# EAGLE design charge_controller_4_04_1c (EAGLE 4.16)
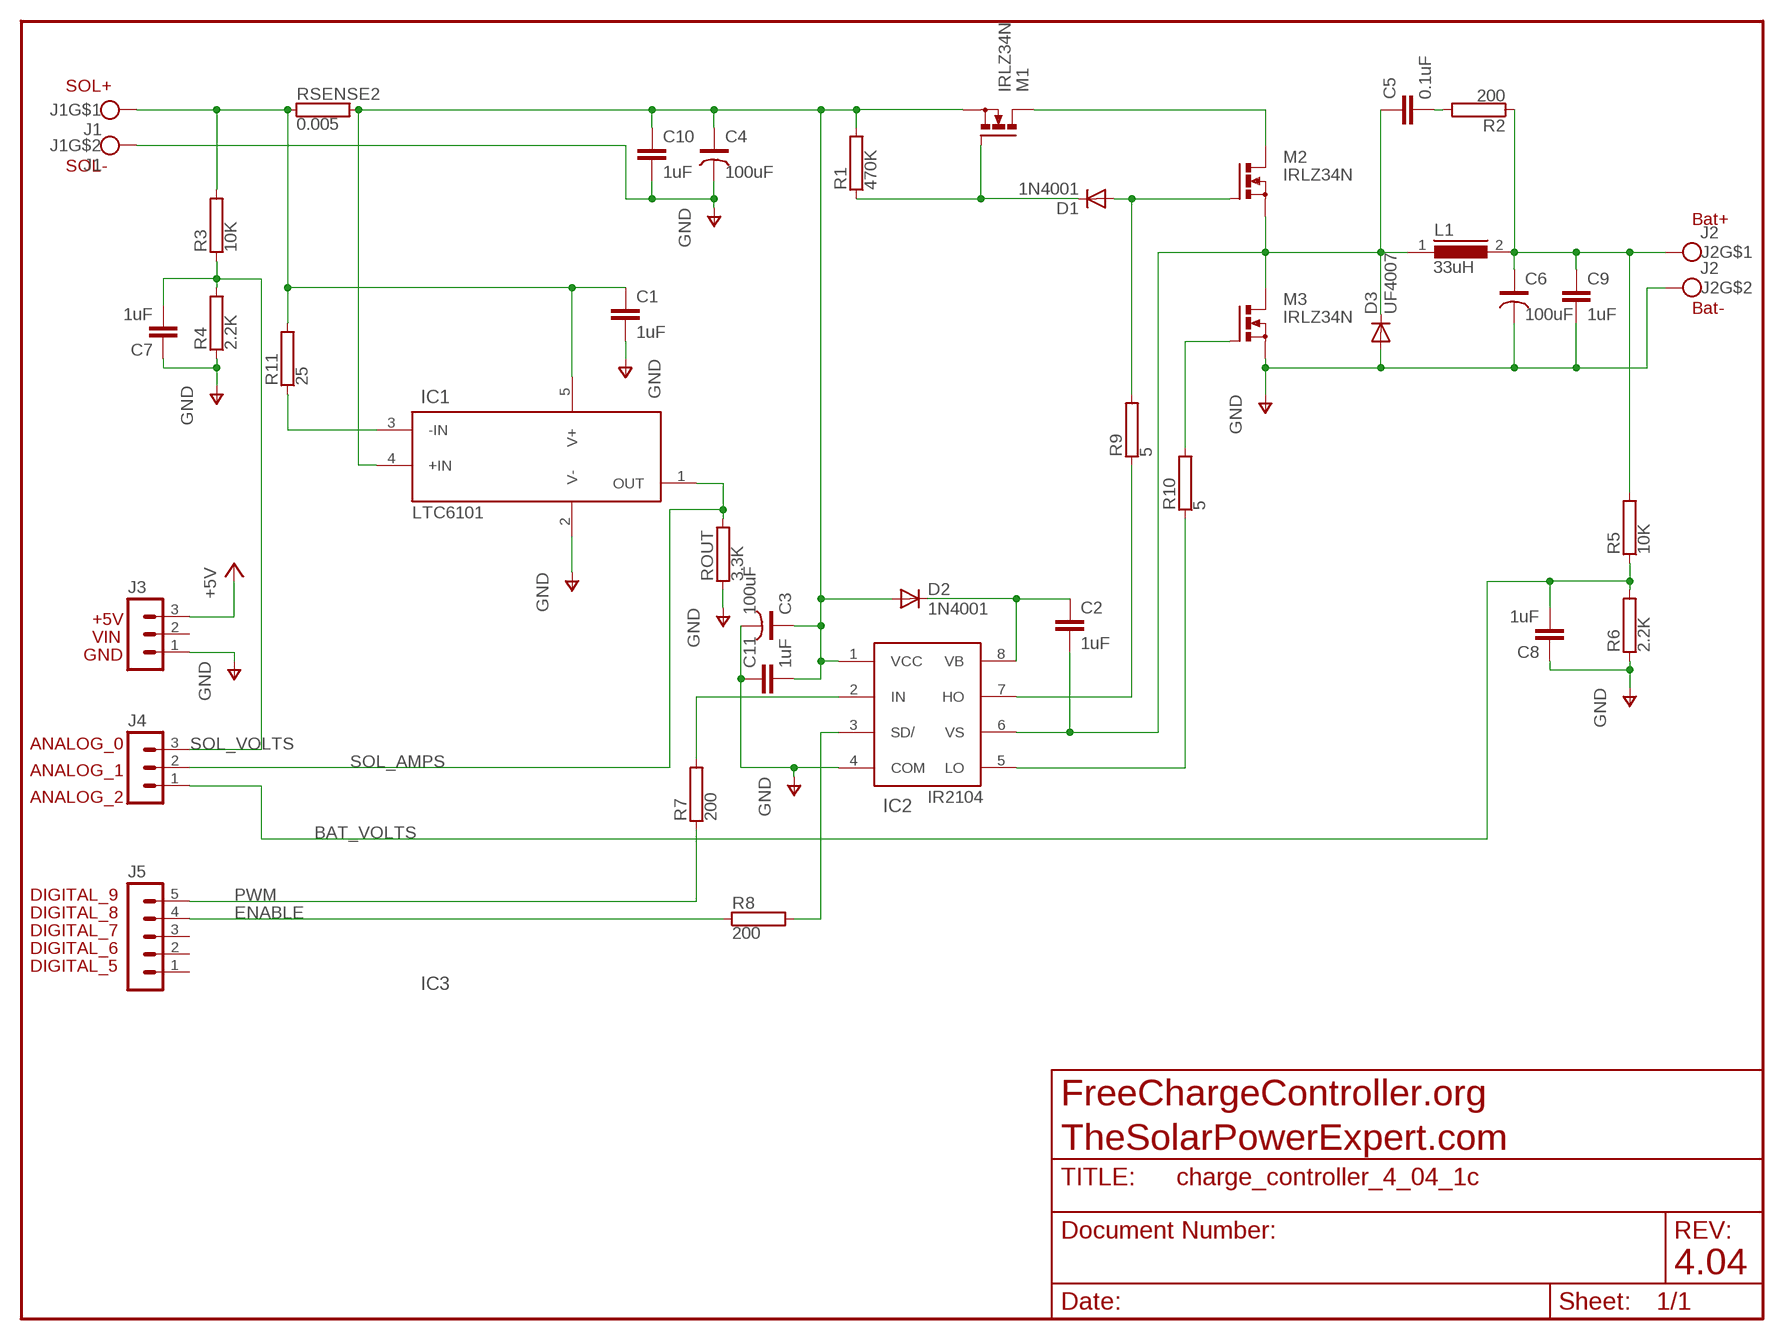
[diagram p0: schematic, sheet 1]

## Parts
C1  1uF  C2.5/2  [C2.5-2]
C2  1uF  C2.5/2  [C2.5-2]
C3  100uF  CAP_POLARIZED  [CAP_POLARIZED]
C4  100uF  CAP_POLARIZED  [CAP_POLARIZED]
C5  0.1uF  C2.5/2  [C2.5-2]
C6  100uF  CAP_POLARIZED  [CAP_POLARIZED]
C7  1uF  C2.5/2  [C2.5-2]
C8  1uF  C2.5/2  [C2.5-2]
C9  1uF  C2.5/2  [C2.5-2]
C10  1uF  C2.5/2  [C2.5-2]
C11  1uF  C2.5/2  [C2.5-2]
D1  1N4001  DIODE  [DO35-10]
D2  1N4001  DIODE  [DO35-10]
D3  UF4007  DIODE  [DO35-10]
IC1  LTC6101B  [TSOT23-5]
IC2  IR2104  [DIP08]
J1  J1  SCREW_TERMINALS  [SCREW_TERMINALS]
J2  J2  SCREW_TERMINALS  [SCREW_TERMINALS]
J3  MA03-1  [MA03-1]
J4  MA03-1  [MA03-1]
J5  MA05-1  [MA05-1]
L1  33uH  A26GFC  [A26GFC]
M1  IRLZ34N  IRFP240  [TO247BV]
M2  IRLZ34N  IRFP240  [TO247BV]
M3  IRLZ34N  IRFP240  [TO247BV]
R1  470K  R  [DO35-10]
R2  200  R  [DO35-10]
R3  10K  R  [DO35-10]
R4  2.2K  R  [DO35-10]
R5  10K  R  [DO35-10]
R6  2.2K  R  [DO35-10]
R7  200  R  [DO35-10]
R8  200  R  [DO35-10]
R9  5  R  [DO35-10]
R10  5  R  [DO35-10]
R11  25  R  [DO35-10]
ROUT  3.3K  R  [DO35-10]
RSENSE2  0.005  RKWP333  [KWP333]

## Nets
+5V: J3.3
BAT_VOLTS: C8.2 J4.1 R5.A R6.C
ENABLE: J5.4 R8.A
N$1: C1.1 IC1.5(V+) J1.1 R3.C R11.C RSENSE2.1
N$2: IC2.3(SD/) R8.C
N$3: IC1.3(-IN) R11.A
N$4: M3.G R10.C
N$5: D1.C M1.G R1.A
N$6: M1.D M2.D
N$7: IC2.7(HO) R9.A
N$8: IC2.2(IN) R7.C
N$9: C3.1 C4.1 C10.1 C11.2 D2.A IC1.4(+IN) IC2.1(VCC) M1.S R1.C RSENSE2.2
N$10: C2.1 D2.C IC2.8(VB)
N$11: C2.2 C5.1 D3.C IC2.6(VS) L1.1 M2.S M3.D
N$12: C6.1 C9.1 J2.1 L1.2 R2.A R5.C
N$13: IC2.5(LO) R10.A
N$14: D1.A M2.G R9.C
N$15: C5.2 R2.C
PWM: J5.5 R7.A
SOL_AMPS: IC1.1(OUT) J4.2 ROUT.C
SOL_VOLTS: C7.2 J4.3 R3.A R4.C
V-: C1.2 C3.2 C4.2 C6.2 C7.1 C8.1 C9.2 C10.2 C11.1 D3.A IC1.2(V-) IC2.4(COM) J1.2 J2.2 J3.1 M3.S R4.A R6.A ROUT.A ; supply symbol labelled GND
Unconnected: J3.2 J5.1 J5.2 J5.3

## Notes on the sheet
- SOL+
- SOL-
- Bat+
- Bat-
- IC1
- LTC6101
- +5V
- VIN
- GND
- ANALOG_0
- ANALOG_1
- ANALOG_2 | IR2104
- IC2
- DIGITAL_9
- DIGITAL_8
- DIGITAL_7
- DIGITAL_6
- DIGITAL_5
- IC3
- FreeChargeController.org
- TheSolarPowerExpert.com
- 4.04

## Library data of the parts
C1 C2 C5 C7-C11 = capacitor-wima:C: CAPACITOR
C3 C4 C6 = MyLibrary:CAP_POLARIZED
D1-D3 = MyLibrary:DIODE
IC1 = MyLibrary:LTC6101B
IC2 = MyLibrary:IR2104: IR2104 MOSFET H-Bridge Driver
J1 J2 = MyLibrary:SCREW_TERMINALS
J3 J4 = con-lstb:MA03-1: PIN HEADER
J5 = con-lstb:MA05-1: PIN HEADER
L1 = inductors:A26GFC: INDUCTOR
M1-M3 = transistor-power:IRFP240: HEXFET Power MosFet Source: http://www.irf.com/
R1-R11 ROUT = resistor-power2:R: Power Resitor
RSENSE2 = resistor-power:R: Power Resitor

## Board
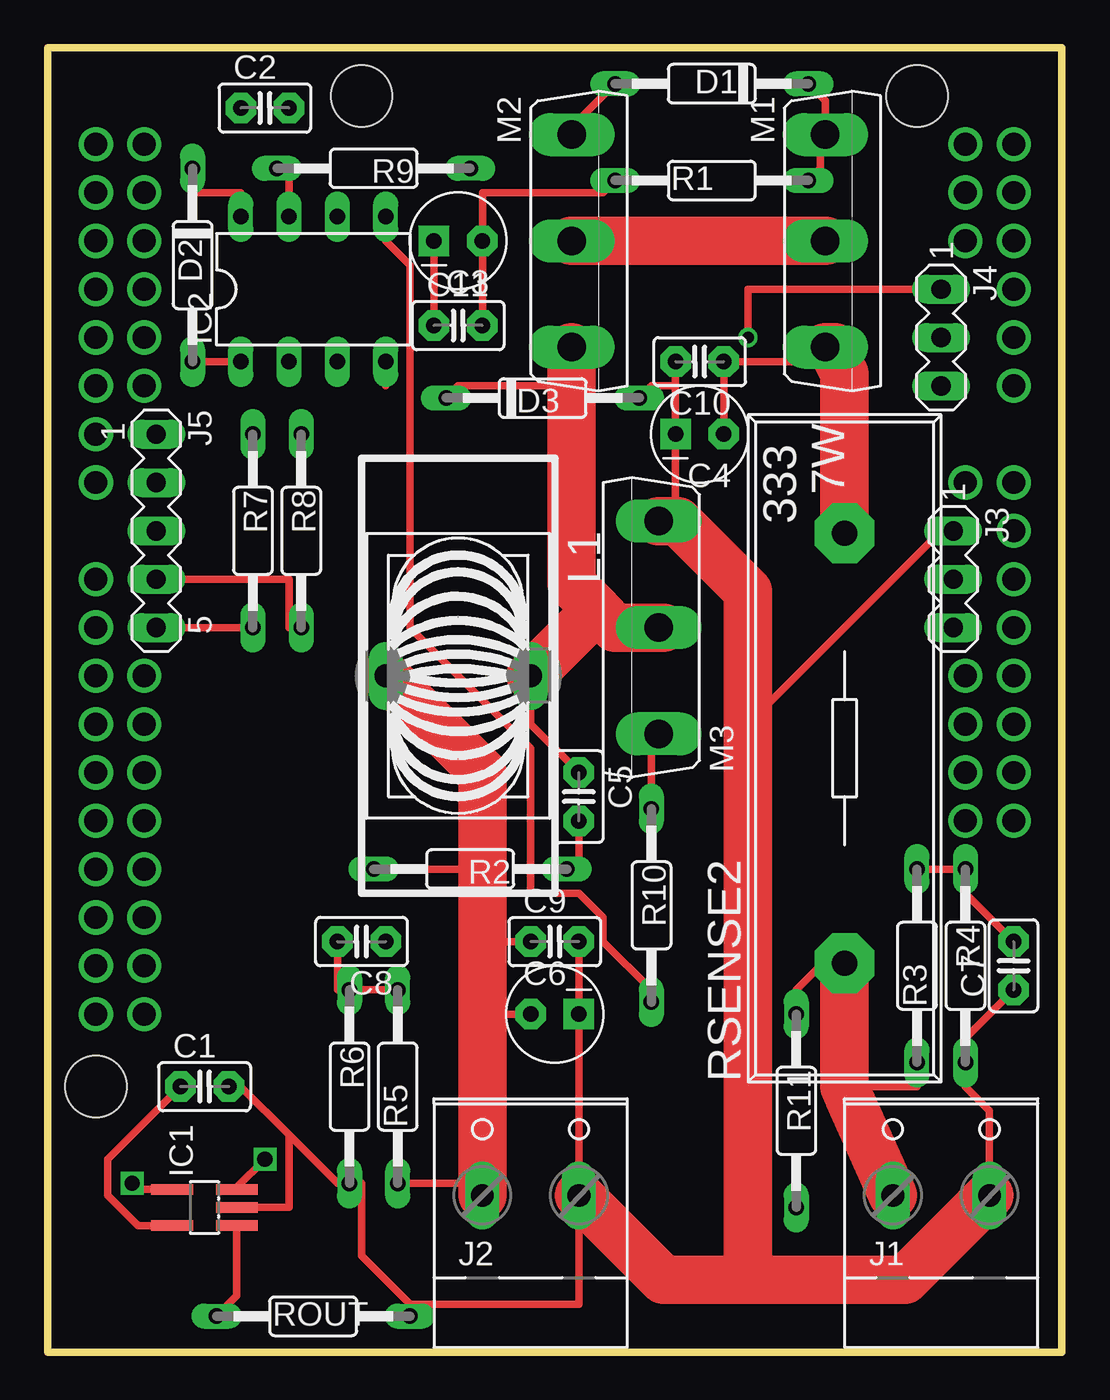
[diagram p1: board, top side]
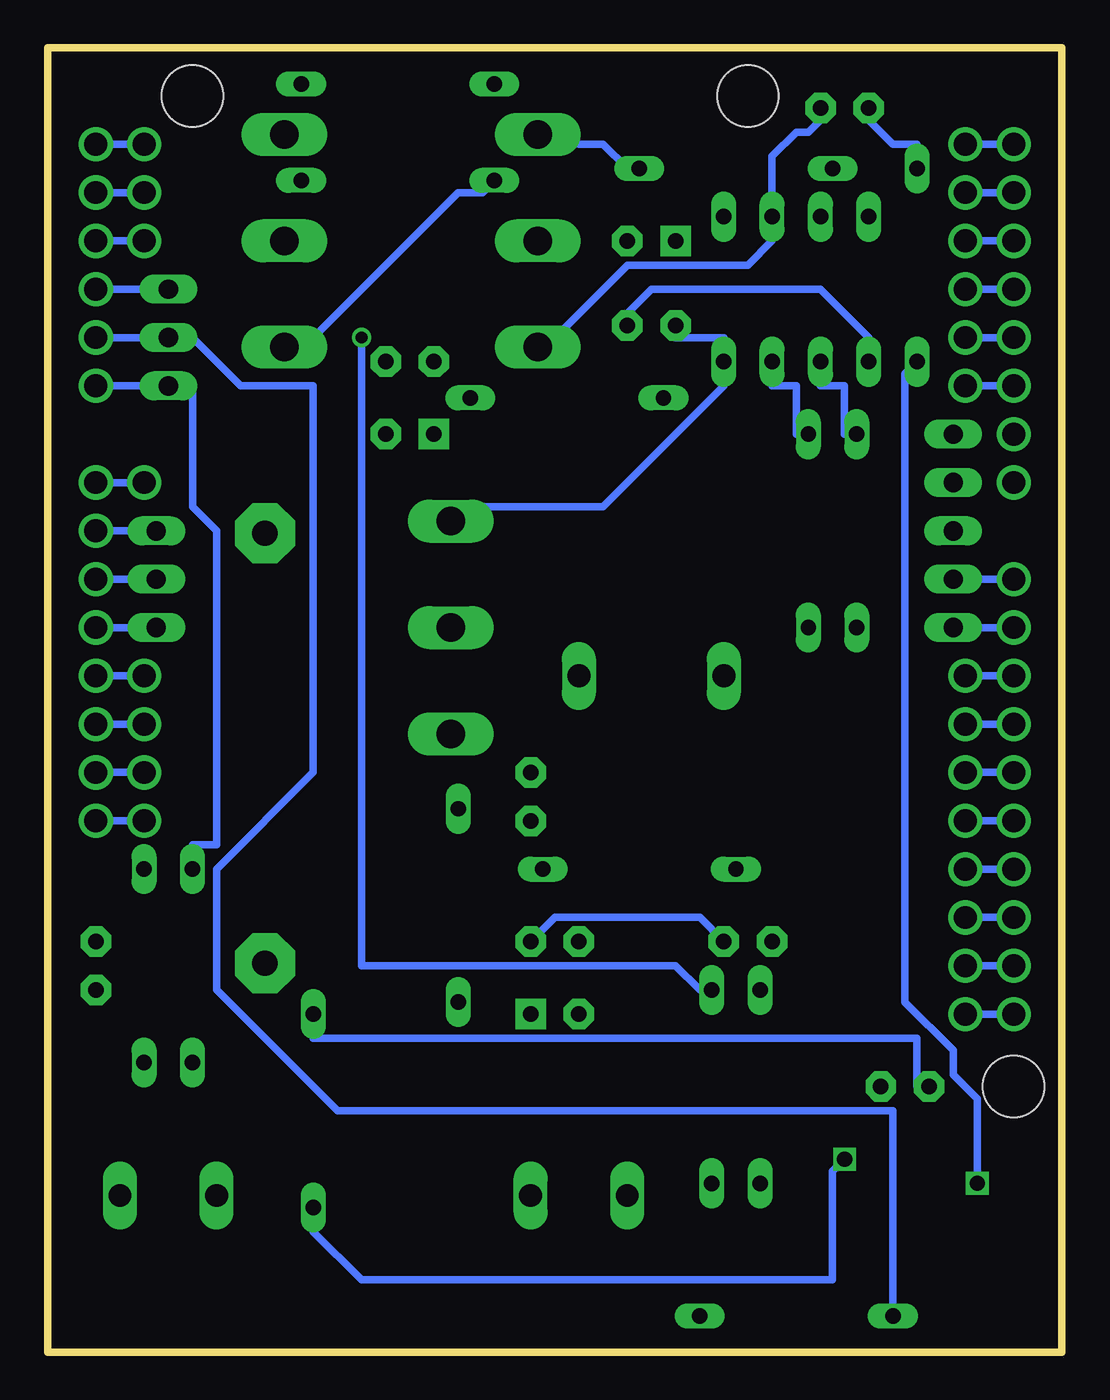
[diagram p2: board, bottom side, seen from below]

Size 53.34 x 68.58 mm. Coordinates in mm from the lower left corner, seen from the top.
Outline: 53.34,0 53.34,68.58 0,68.58 0,0 53.34,0
Copper layers (1*16): Top 0.035mm / dielectric 1.5mm / Bottom 0.035mm
Design rules "default": minimum track width 16mil, minimum drill 24mil, track to track 8mil, track to pad 8mil, pad to pad 8mil, via to via 8mil, smd to smd 8mil, copper to edge 40mil, drill to drill 8mil, minimum pad ring 10mil, minimum via ring 8mil, stop-mask expansion 4mil, vias tented up to drill 0mil, thermal gap 10mil
Holes 3.23 mm at 45.72,66.04 16.51,66.04 2.54,13.97

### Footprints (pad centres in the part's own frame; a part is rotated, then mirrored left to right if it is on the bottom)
C2.5-2 = drill 0.813 pad 1.6 octagon: 1 -1.27,0; 2 1.27,0
CAP_POLARIZED = drill 0.813 pad 1.6 octagon: 1 -1.27,0 | drill 0.813 pad 1.6 square: 2 1.27,0
DO35-10 = drill 0.813 long: A 5.08,0; C -5.08,0
TSOT23-5 = smd 0.55 x 2.2: 1 -0.95,-1.7; 2 0,-1.7; 3 0.95,-1.7; 4 0.95,1.7; 5 -0.95,1.7
DIP08 = drill 0.813 long: 1 -3.81,-3.81; 2 -1.27,-3.81; 3 1.27,-3.81; 4 3.81,-3.81; 5 3.81,3.81; 6 1.27,3.81; 7 -1.27,3.81; 8 -3.81,3.81
SCREW_TERMINALS = drill 1.194 long: 1 -2.54,-0.635; 2 2.54,-0.635
MA03-1 = drill 1.016 long: 1 -2.54,0; 2 0,0; 3 2.54,0
MA05-1 = drill 1.016 long: 1 -5.08,0; 2 -2.54,0; 3 0,0; 4 2.54,0; 5 5.08,0
A26GFC = drill 1.194 long: 1 0,3.81; 2 0,-3.81
TO247BV = drill 1.499 long: D 0,-2.921; G -5.588,-2.921; S 5.588,-2.921
KWP333 = drill 1.321 pad 3.15 octagon: 1 -11.303,0; 2 11.303,0

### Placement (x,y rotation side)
C1  8.26,13.97 0 top
C2  11.43,65.41 0 top
C3  21.59,58.42 180 top
C4  34.29,48.26 180 top
C5  27.94,29.21 270 top
C6  26.67,17.78 0 top
C7  50.8,20.32 90 top
C8  16.51,21.59 180 top
C9  26.67,21.59 0 top
C10  34.29,52.07 180 top
C11  21.59,53.98 0 top
D1  34.92,66.67 180 top
D2  7.62,57.15 270 top
D3  26.04,50.16 0 top
IC1  8.26,7.62 90 top
IC2  13.97,55.88 0 top
J1  46.99,8.89 0 top
J2  25.4,8.89 0 top
J3  47.62,40.64 270 top
J4  46.99,53.34 270 top
J5  5.71,43.18 270 top
L1  21.59,35.56 270 top
M1  43.81,58.42 270 top
M2  30.48,58.42 270 top
M3  29.21,38.1 90 top
R1  34.92,61.59 0 top
R2  22.23,25.4 180 top
R3  45.72,20.32 90 top
R4  48.26,20.32 270 top
R5  18.41,13.97 90 top
R6  15.88,13.97 270 top
R7  10.79,43.18 270 top
R8  13.34,43.18 270 top
R9  17.14,62.23 180 top
R10  31.75,23.5 270 top
R11  39.37,12.7 270 top
ROUT  13.97,1.91 0 top
RSENSE2  41.91,31.75 90 top

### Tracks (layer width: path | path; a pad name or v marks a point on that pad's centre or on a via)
BAT_VOLTS  (via drill 0.61, 1.2)
  Top 0.406: R5.A R6.C 15.24,19.05 C8.2 | v36.83,53.34 36.83,55.88 J4.1
  Bottom 0.406: J4.1 v50.8,55.88 | v36.83,53.34 36.83,20.32 20.32,20.32 19.05,19.05 R5.A
ENABLE
  Top 0.406: R8.A 12.7,38.1 12.7,40.64 J5.4
N$1
  Top 0.406: R11.C 39.37,19.05 40.64,20.32 RSENSE2.1 | R3.C 45.72,13.97 43.18,13.97 42.12,13.5 | IC1.5 4.76,6.67 3.17,8.26 3.17,10.16 C1.1
  Top 2.54: J1.1 42.12,13.5 41.91,13.97 RSENSE2.1
  Bottom 0.406: C1.1 7.62,13.97 7.62,16.51 39.37,16.51 R11.C
N$2
  Bottom 0.406: R8.C 13.97,48.26 13.97,50.8 15.24,50.8 IC2.3
N$3  (via drill 0.8)
  Top 0.406: IC1.3 9.96,8.69 v11.43,10.16
  Bottom 0.406: R11.A 39.37,6.35 36.83,3.81 12.06,3.81 12.06,9.53 v11.43,10.16
N$4
  Top 0.406: R10.C 31.75,31.75 M3.G
N$5
  Top 0.406: R1.A 40.64,62.23 40.64,63.5 M1.G 40.89,65.79 D1.C
N$6
  Top 2.54: M2.D M1.D
N$7
  Top 0.406: R9.A 12.7,62.23 IC2.7
N$8
  Bottom 0.406: R7.C 11.43,48.26 11.43,50.8 12.7,50.8 IC2.2
N$9  (via drill 0.8)
  Top 0.406: C4.1 C10.1 39.37,52.07 M1.S | R1.C 29.21,60.96 22.86,60.96 C3.1 C11.2 | D2.A IC2.1 | IC1.4 4.76,8.57 v4.45,8.89
  Top 2.54: M1.S 41.4,52.83 41.27,52.7 41.91,51.44 RSENSE2.2
  Bottom 0.406: IC2.1 10.16,53.34 12.7,55.88 21.59,55.88 22.86,54.61 C11.2 | M1.S 39.37,53.34 31.75,60.96 30.48,60.96 R1.C | D2.A 8.26,51.44 8.26,18.41 5.71,15.88 5.71,14.61 4.45,13.34 v4.45,8.89
N$10
  Top 0.406: D2.C 7.62,60.96 10.16,60.96 IC2.8
  Bottom 0.406: C2.1 10.16,64.77 8.89,63.5 7.62,63.5 D2.C
N$11
  Top 0.406: C5.1 25.4,33.02 L1.1 | D3.C 21.59,50.8 27.56,50.8
  Top 2.54: M2.S 27.56,50.8 27.56,40.39 28.89,39.05 | 28.89,39.05 29.84,38.1 M3.D 32.38,38.1 | L1.1 28.89,39.05
  Bottom 0.406: C2.2 12.7,64.77 13.34,64.14 13.97,64.14 15.24,62.87 IC2.6 15.24,58.42 16.51,57.15 22.86,57.15 26.67,53.34 M2.S
N$12
  Top 0.406: R5.C 22.86,8.89 | 22.86,25.4 R2.A | 22.86,17.78 C6.1 | 22.86,21.59 C9.1
  Top 2.54: J2.1 22.86,8.89 22.86,17.78 22.86,21.59 22.86,25.4 22.86,30.48 L1.2
N$13
  Top 0.406: R10.A 31.75,19.05 29.21,21.59 29.21,22.86 27.94,24.13 25.4,24.13 25.4,31.75 19.05,38.1 19.05,57.15 17.78,58.42 IC2.5
N$14
  Top 0.406: M2.G 27.56,64.39 D1.A
  Bottom 0.406: R9.C 22.86,62.23 24.13,63.5 25.4,63.5 M2.G
N$15
  Top 0.406: C5.2 27.94,25.4 R2.C
N$17  (via drill 1.2)
  Bottom 0.406: v2.54,38.1 6.35,38.1
N$30  (via drill 1.2)
  Bottom 0.406: v2.54,63.5 v5.08,63.5
N$31  (via drill 1.2)
  Bottom 0.406: v2.54,60.96 v5.08,60.96
N$32  (via drill 1.2)
  Bottom 0.406: v2.54,58.42 v5.08,58.42
N$33  (via drill 1.2)
  Bottom 0.406: v2.54,55.88 v5.08,55.88
N$34  (via drill 1.2)
  Bottom 0.406: v2.54,53.34 v5.08,53.34
N$35  (via drill 1.2)
  Bottom 0.406: v2.54,50.8 v5.08,50.8
N$36  (via drill 1.2)
  other vias: 2.54,48.26
N$37  (via drill 1.2)
  other vias: 2.54,45.72
N$38  (via drill 1.2)
  Bottom 0.406: v2.54,40.64 6.35,40.64
N$40  (via drill 1.2)
  Bottom 0.406: v2.54,35.56 v5.08,35.56
N$41  (via drill 1.2)
  Bottom 0.406: v2.54,33.02 v5.08,33.02
N$42  (via drill 1.2)
  Bottom 0.406: v2.54,30.48 v5.08,30.48
N$43  (via drill 1.2)
  Bottom 0.406: v2.54,27.94 v5.08,27.94
N$44  (via drill 1.2)
  Bottom 0.406: v2.54,25.4 v5.08,25.4
N$45  (via drill 1.2)
  Bottom 0.406: v2.54,22.86 v5.08,22.86
N$46  (via drill 1.2)
  Bottom 0.406: v2.54,20.32 v5.08,20.32
N$47  (via drill 1.2)
  Bottom 0.406: v2.54,17.78 v5.08,17.78
N$66  (via drill 1.2)
  Bottom 0.406: v48.26,27.94 v50.8,27.94
N$67  (via drill 1.2)
  Bottom 0.406: v48.26,30.48 v50.8,30.48
N$68  (via drill 1.2)
  Bottom 0.406: v48.26,33.02 v50.8,33.02
N$69  (via drill 1.2)
  Bottom 0.406: v48.26,35.56 v50.8,35.56
N$70  (via drill 1.2)
  Bottom 0.406: 46.99,38.1 v50.8,38.1
N$71  (via drill 1.2)
  Bottom 0.406: 46.99,40.64 v50.8,40.64
N$72  (via drill 1.2)
  Bottom 0.406: 46.99,43.18 v50.8,43.18
N$73  (via drill 1.2)
  Bottom 0.406: v48.26,45.72 v50.8,45.72
N$77  (via drill 1.2)
  Bottom 0.406: v48.26,58.42 v50.8,58.42
N$78  (via drill 1.2)
  Bottom 0.406: v48.26,60.96 v50.8,60.96
N$79  (via drill 1.2)
  Bottom 0.406: v48.26,63.5 v50.8,63.5
PWM
  Top 0.406: J5.5 R7.A
SOL_AMPS  (via drill 1.2)
  Top 0.406: IC1.1 9.96,2.97 ROUT.C
  Bottom 0.406: v50.8,53.34 J4.2 45.72,53.34 43.18,50.8 39.37,50.8 39.37,30.48 44.45,25.4 44.45,19.05 38.1,12.7 8.89,12.7 ROUT.C
SOL_VOLTS  (via drill 1.2)
  Top 0.406: R3.A R4.C 48.26,24.13 C7.2
  Bottom 0.406: v50.8,50.8 J4.3 45.72,50.8 45.72,44.45 44.45,43.18 44.45,26.67 45.72,26.67 R3.A
V-
  Top 0.406: 12.7,11.43 15.24,8.89 R6.A 16.51,8.89 16.51,5.08 19.05,2.54 | 12.7,11.43 10.16,13.97 C1.2 | C11.1 C3.2 | IC2.4 17.78,50.8 | C9.2 C6.2 J2.2 27.94,2.54 19.05,2.54 | C7.1 48.26,16.51 R4.A 48.26,13.97 49.53,12.7 J1.2 | 33.02,50.8 C4.2 33.02,44.45 M3.S | 33.02,50.8 C10.2 | 36.83,33.02 46.99,43.18 J3.1 | 19.05,2.54 ROUT.A | 12.7,11.43 12.7,7.62 IC1.2 | 33.02,50.8 31.75,50.8 D3.A
  Top 2.54: J2.2 32.38,3.81 36.83,3.81 | 36.83,3.81 45.09,3.81 J1.2 | M3.S 33.15,43.69 36.83,40.01 36.83,33.02 36.83,3.81
  Bottom 0.406: C11.1 20.32,53.34 17.78,53.34 IC2.4 17.78,50.8 24.13,44.45 30.48,44.45 M3.S | C8.1 19.05,22.86 26.67,22.86 C9.2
